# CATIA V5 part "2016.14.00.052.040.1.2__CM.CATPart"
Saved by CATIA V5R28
Part number: 2016.14.00.052.040.1.2__CM
Property "id_number": "2016.14.00.052.040.1.2"
Publications: "Absolute Axis System", "driver", "slider", "base", "cam diagram"
Bounding box of the stored display mesh (mm): x -40 to 135, y -49 to 49, z 0 to 180
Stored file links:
  N:\B2\Normteile\K\2016\11-14\005\cm\2016.14.00.052.040.1.2__CM.CATPart
  H:\CAD_Startmodelle\Tests\fill-in_PRT-SL_TEMPLATE.xlsx
  H:\CAD_Startmodelle\V5-R24\R24_TEMPLATE_PRT_FIBRO_CAM_TECNOLOGIES_INDEX.xlsx
  H:\z_Einordnen\170511__Anfrage_TK_HN\170511__CC01_TKHN.CATPart
  N:\B2\Normteile\K\2016\9xxx\2016.9024.1705.001\Entwurf_\170511__CC01_TKHN.CATPart
  N:\B2\Normteile\K\2016\9xxx\2016.9024.1707.006\Konstruktion\2016.9024.1707.006__HP__CUSTOMIZED_CAM_CM.CATPart
  N:\B2\Normteile\K\2016\9xxx\2016.9024.1707.005\Konstruktion\2016.9024.1707.005__HP__CUSTOMIZED_CAM_CM.CATPart
  N:\B2\Normteile\K\2016\9xxx\2016.9024.1707.008\Konstruktion\2016.9024.1707.008__HP__CUSTOMIZED_CAM_CM.CATPart
  N:\B2\Normteile\K\2016\9xxx\2016.9024.1707.009\Konstruktion\2016.9024.1707.009__HP__CUSTOMIZED_CAM_CM.CATPart
  N:\B2\Normteile\K\2016\9xxx\2016.9024.1707.010\Konstruktion\2016.9024.1707.010__HP__CUSTOMIZED_CAM_CM.CATPart
  N:\B2\Normteile\K\2016\9xxx\2016.9024.1708.002\Konstruktion\2016.9024.1708.002__HP__CUSTOMIZED_CAM_CM.CATPart
  N:\B2\Normteile\K\2016\9xxx\2016.9024.1802.001\Konstruktion\2016.9024.1802.001__HP__CUSTOMIZED_CAM_CM.CATPart
  N:\B2\Normteile\K\2016\9xxx\2016.9024.1802.002\Konstruktion\2016.9024.1802.002__HP__CUSTOMIZED_CAM_CM.CATPart
  N:\B2\Normteile\K\2016\9xxx\2016.9024.1811.003\Konstruktion\2016.9024.1811.003__HP__CUSTOMIZED_CAM_CM.CATPart
  N:\B2\Normteile\K\2016\9xxx\2016.9015.1811.001\Konstruktion\am\2016.9015.1811.001__AM__FCC_HV_DMC_0125-00.CATPart
  N:\B2\Normteile\K\2016\9xxx\2016.9024.1811.009\Konstruktion\2016.9024.1811.009__HP__CUSTOMIZED_CAM_CM.CATPart
  N:\B2\Normteile\K\2016\9xxx\2016.9024.1911.002\Konstruktion\am\2016.9024.1911.002__AM__CUSTOMIZED_CAM_CM.CATPart
  N:\B2\Normteile\K\2016\9xxx\2016.9024.2002.006\Konstruktion\2016.9024.2002.006__AM.CATPart
  N:\B2\Normteile\K\2016\9xxx\2016.9024.2004.001\Konstruktion\2016.9024.2004.001__AM__FCC_HV_CAEC_0260-45.CATPart
  N:\B2\Normteile\K\2016\9xxx\2016.9024.2006.002\Konstruktion\2016.9024.2006.002__AM__FCC_HV_CAEC_0260-40.CATPart
  N:\B2\Normteile\K\2016\9xxx\2016.9024.2006.005\Konstruktion\am\2016.9024.2006.005__AM__CFCC_HV_AEPC_0080-65.CATPart
  N:\B2\Normteile\K\2016\9xxx\2016.9024.2006.004\Konstruktion\am\2016.9024.2006.004__AM__CFCC_HV_AEC_0210-35.CATPart
  N:\B2\Normteile\K\2016\9xxx\2016.9026.2006.001\Konstruktion\am\2016.9026.2006.001__AM__FCC_LV_CAEC_0180-40.CATPart
  N:\B2\Normteile\K\2016\9xxx\2016.9015.2007.001\Konstruktion\am\2016.9015.2007.001__AM__FCC_HV_CDMPC_0090-00.CATPart
  N:\B2\Normteile\K\2016\9xxx\2016.9024.2005.001\Konstruktion\am\2016.9024.2005.001__AM__CFCC_HV_AEPC_1400-70.CATPart
  N:\B2\Normteile\K\2016\9xxx\2016.9024.2007.004\Konstruktion\am\2016.9024.2007.004__AM__CFCC_HV_AEC_1250-80.CATPart
  N:\B2\Normteile\K\2016\11-14\005\2016.11.00.052.040.1.02__AS__DIE_MOUNT_CAM__W52_A0_S40.CATProduct
  N:\B2\Normteile\K\2016\11-14\005\cm\2016.11.00.052.025.1.2__CM.CATPart
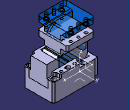
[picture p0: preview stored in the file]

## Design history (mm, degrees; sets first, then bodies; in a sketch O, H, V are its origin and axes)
Parameters
  group "process_parameters"
    modeltype = ""
    stocklist = ""
    id_number = "2016.14.00.052.040.1.2"
    id_number_rough_part = ""
    revision_index = ""
    revision_date = ""
    revision_description = ""
    category = ""
    material = ""
    manufacturing_information = ""
    standard = ""
  group "release_parameters_startmodel"
    sm_revision_index = "2016_00" {design table}
    sm_revision_date = "20.08.2016" {design table}
    sm_revision_name = "Meyer" {design table}
    sm_revision_description = "new part template FIBRO cam tecnologies" {design table}
AxisSystem1: origin (0, 0, 0), X (1, 0, 0), Y (0, 1, 0), Z (0, 0, 1)
Set1 "reference elements"
  Sketch1 "cam diagram" on ZX plane of AxisSystem1, origin (0, 0, 0), H (-1, 0, 0), V (0, 0, 1)
    line L1 (0, 0) -> (40, 0)
    line L2 (40, 0) -> (0, 40)
    point P2 (0, 40)
    line L3 (0, 40) -> (0, 0)
    length L1 = 40
    angle H L2 = 45
    horizontal: L1 H
    coincidence: P2 V
    vertical: L3 V
Body1 "finished_part" (main body)
  Body2 "rough_part"
  Add1 "rough_part": tool Body2
  Body3 "milling operations"
  Remove1 "milling operations": tool Body3
  Body4 "drilling operations"
  Remove2 "drilling operations": tool Body4
Body5 "driver"
  Solid1: solid without history
Body6 "slider"
  Solid2: solid without history
Body7 "base"
  Solid3: solid without history
Body8 "opened position"
  Body9 "slider"
    Body10 "slider"
      Solid4: linked copy from another document
    Assemble1: tool Body10
    Translate1: FirstPoint vertex [element of Sketch1 | element of Sketch1], SecondPoint vertex [element of Sketch1 | element of Sketch1], ToTransfor Assemble1
  Assemble2: tool Body9
  Body11 "driver"
    Body12 "driver"
      Solid5: linked copy from another document
    Assemble3: tool Body12
    Translate2: FirstPoint vertex [element of Sketch1 | element of Sketch1], SecondPoint vertex [element of Sketch1 | element of Sketch1], ToTransfor Assemble3
  Assemble4: tool Body11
